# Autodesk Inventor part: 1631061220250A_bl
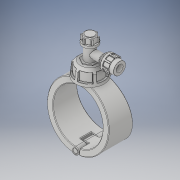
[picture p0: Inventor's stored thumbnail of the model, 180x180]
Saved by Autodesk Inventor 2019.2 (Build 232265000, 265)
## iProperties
Created: 2022-02
Part Number: 1631061220250A_bl
Material: Generic
Description: Plassadle Tapper 177x25
Document SubType Name: Modeling
Designer: comp2
Density: 1 g/cm^3
Appearance: Default
Author: comp2
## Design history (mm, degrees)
derived "16310.ipt"
feature "Solid1::16310.ipt" dims "ScaleForDerivedMember" = 10
feature "Solid2::16310.ipt" dims "ScaleForDerivedMember" = 10
feature "Solid3::16310.ipt" dims "ScaleForDerivedMember" = 10
feature "Solid4::16310.ipt" dims "ScaleForDerivedMember" = 10
tag "TaggingFeature1"
body "Solid1"
body "Solid2"
body "Solid3"
body "Solid4"
other parameters: "d0" = 177 [user parameter], "d3" = 88.5 [user parameter], "d7" = 209 [user parameter], "d8" = 85 deg [user parameter], "d9" = 45 deg [user parameter], "d10" = 102 [user parameter], "d11" = 52 [user parameter], "d12" = 36.4 [user parameter], "d13" = 35.7 [user parameter], "d14" = 55.08 [user parameter], "d15" = 2.6 [user parameter], "d16" = 2 [user parameter], "d17" = 2 [user parameter], "d18" = 31.2 [user parameter], "d19" = 7.8 [user parameter], "d20" = 1 [user parameter], "d21" = 30.6 [user parameter], "d22" = 1 [user parameter], "d23" = 15.6 [user parameter], "d24" = 106 [user parameter], "d27" = 144 [user parameter], "d29" = 54 [user parameter], "d31" = 43.2 [user parameter], "d32" = 42.4 [user parameter], "d33" = 14.84 [user parameter], "d34" = 93 deg [user parameter], "d35" = 2 [user parameter], "d36" = 4 [user parameter], "d39" = 45 deg [user parameter], "d40" = 4 [user parameter], "d41" = 5 [user parameter], "d42" = 4.3 [user parameter], "d46" = 51 [user parameter], "d47" = 27 [user parameter], "d48" = 52 [user parameter], "d49" = 4.4 [user parameter], "d51" = 0 [user parameter], "d52" = 30.1 [user parameter], "d53" = 121 [user parameter], "d54" = 38.5 [user parameter], "d55" = 0 [user parameter], "d56" = 22 [user parameter], "d57" = 22 [user parameter], "d59" = 0 [user parameter], "d61" = 0 [user parameter], "d62" = 38.5 [user parameter], "d63" = 0 [user parameter], "d65" = 0 [user parameter], "d67" = 0 [user parameter], "d69" = 0 [user parameter], "d70" = 1 [user parameter], "d71" = 105.6 [user parameter], "d72" = 0 [user parameter], "d73" = 2 [user parameter], "d77" = 25 [user parameter], "d78" = 86.7 [user parameter], "d79" = 5.1 [user parameter], "d80" = 60 deg [user parameter], "d81" = 5.1 [user parameter], "d84" = 0 [user parameter], "d85" = 1 [user parameter], "d87" = 360 deg [user parameter], "d90" = 0 [user parameter], "d91" = 1 [user parameter], "d93" = 60 deg [user parameter], "d94" = 3.06 [user parameter], "d95" = 3.06 [user parameter], "d97" = 0 [user parameter], "d98" = 0.5 [user parameter], "d100" = 360 deg [user parameter], "d102" = 2 [user parameter], "d105" = 0 [user parameter], "d106" = 45 deg [user parameter], "d107" = 2.7 [user parameter], "d108" = 2.7 [user parameter], "d109" = 2.95332 [user parameter], "d110" = -8 [user parameter], "d112" = 0 [user parameter], "d113" = 0.5 [user parameter], "d115" = 360 deg [user parameter], "d117" = 0.5 [user parameter], "d" = 177 [user parameter], "d1" = 25 [user parameter], "E_" = 54 [user parameter], "E1" = 102 [user parameter], "H2" = 144 [user parameter], "H3" = 106 [user parameter], "H_costum" = 52 [user parameter]
